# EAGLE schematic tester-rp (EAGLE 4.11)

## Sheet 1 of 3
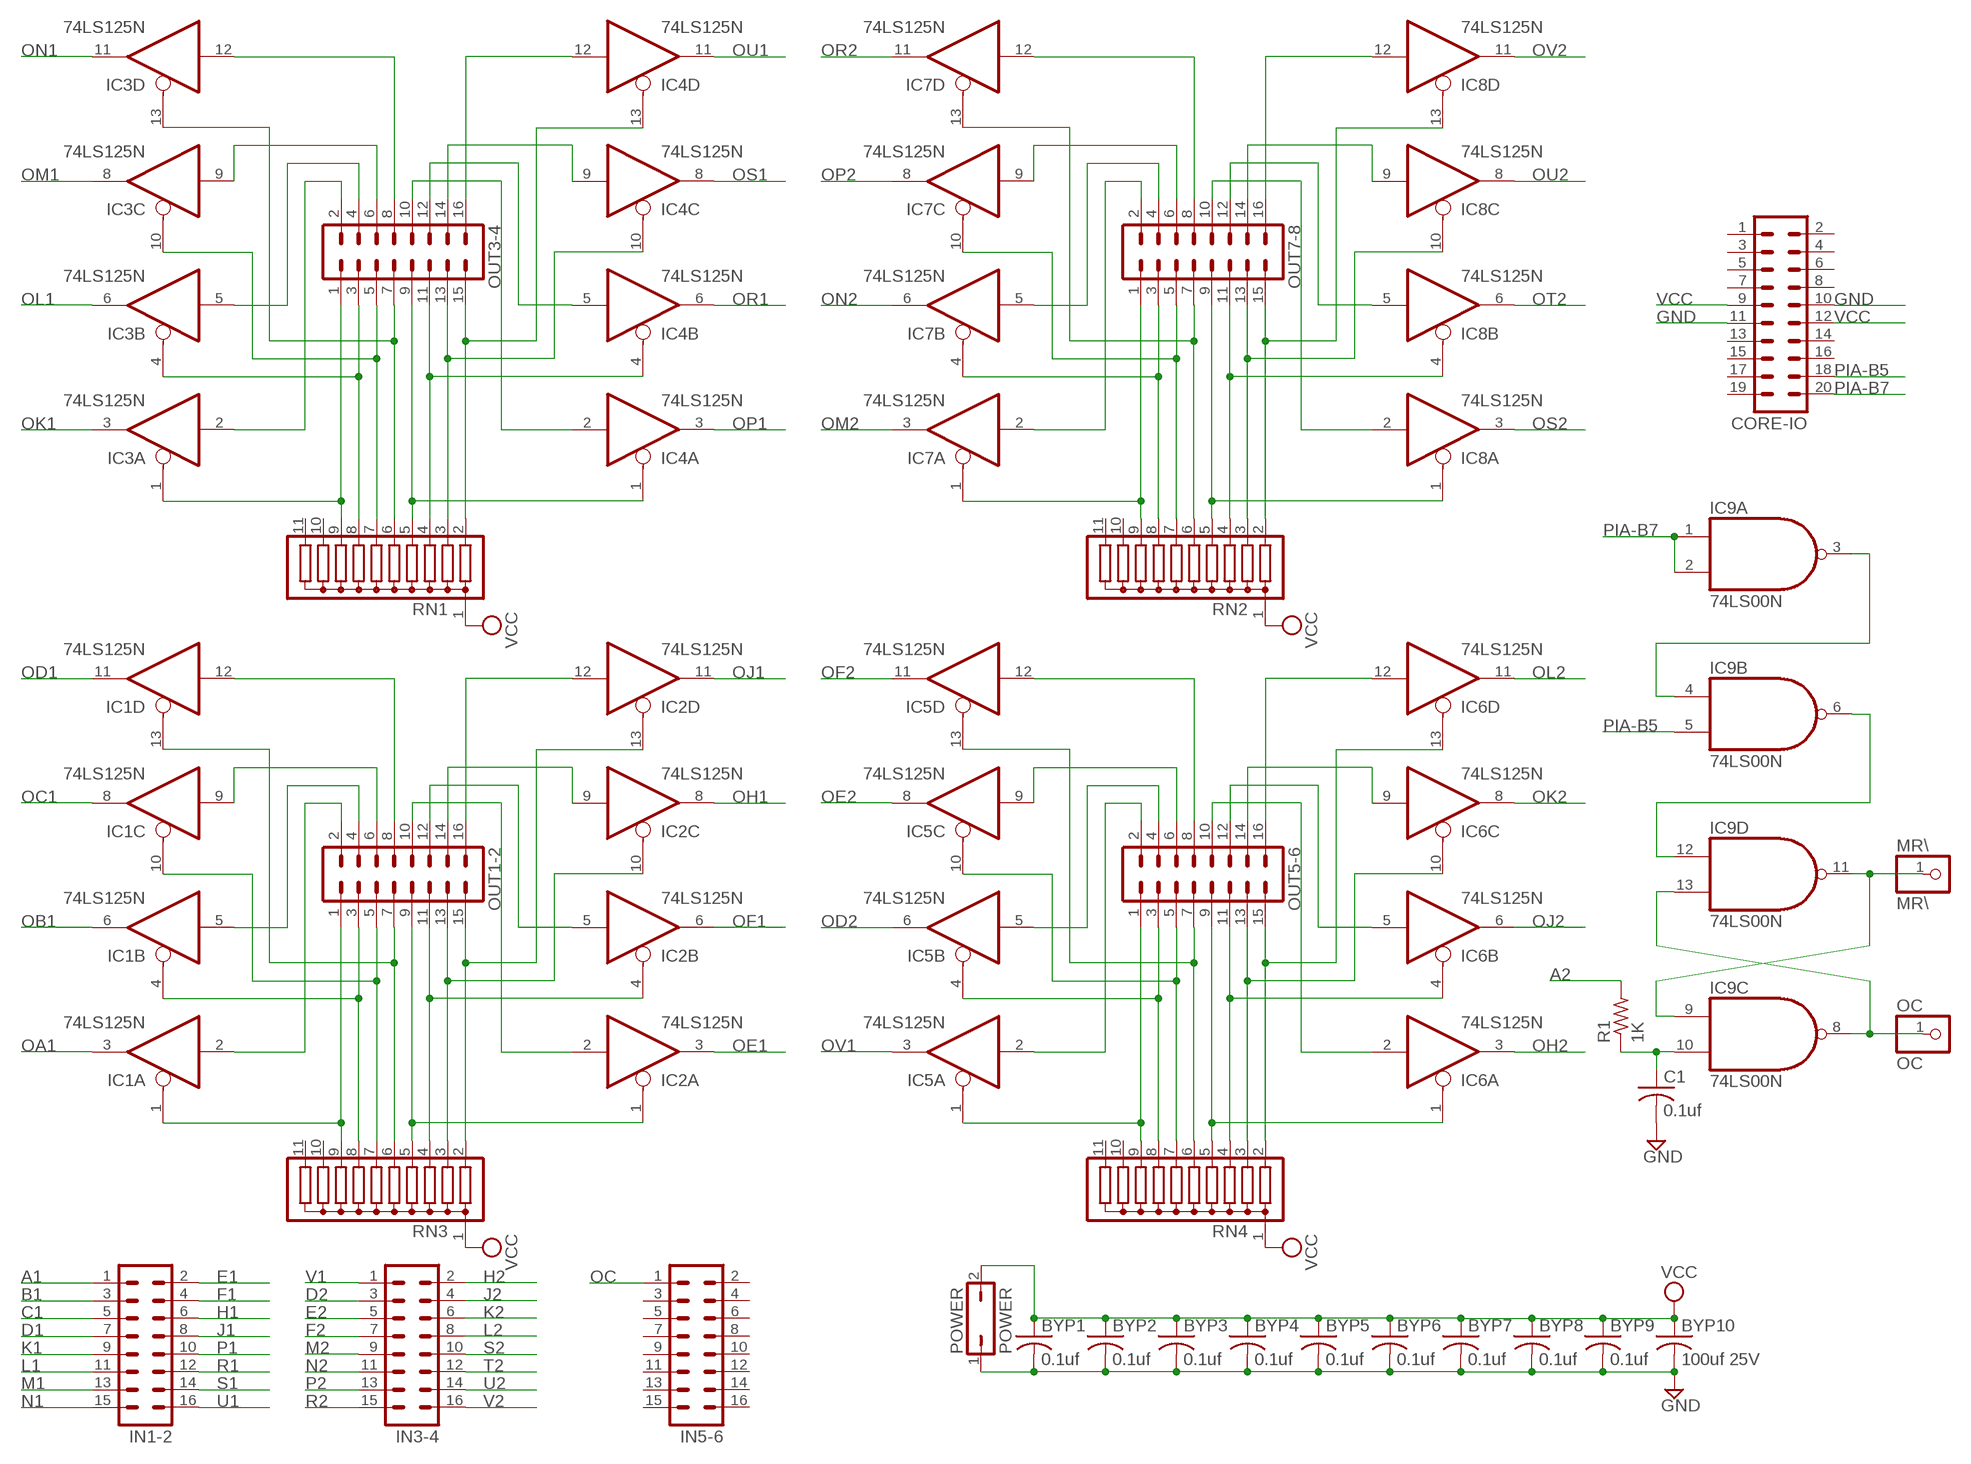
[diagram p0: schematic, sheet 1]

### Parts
BYP1  0.1uf  C-US050-025X075  [C050-025X075]
BYP2  0.1uf  C-US050-025X075  [C050-025X075]
BYP3  0.1uf  C-US050-025X075  [C050-025X075]
BYP4  0.1uf  C-US050-025X075  [C050-025X075]
BYP5  0.1uf  C-US050-025X075  [C050-025X075]
BYP6  0.1uf  C-US050-025X075  [C050-025X075]
BYP7  0.1uf  C-US050-025X075  [C050-025X075]
BYP8  0.1uf  C-US050-025X075  [C050-025X075]
BYP9  0.1uf  C-US050-025X075  [C050-025X075]
BYP10  100uf 25V  C-US150-064X183  [C150-064X183]
C1  0.1uf  C-US050-025X075  [C050-025X075]
CORE-IO  MA10-2  [MA10-2]
IC1  74LS125N  [DIL14]
IC2  74LS125N  [DIL14]
IC3  74LS125N  [DIL14]
IC4  74LS125N  [DIL14]
IC5  74LS125N  [DIL14]
IC6  74LS125N  [DIL14]
IC7  74LS125N  [DIL14]
IC8  74LS125N  [DIL14]
IC9  74LS00N  [DIL14]
IN1-2  MA08-2  [MA08-2]
IN3-4  MA08-2  [MA08-2]
IN5-6  MA08-2  [MA08-2]
MR\  MR\  PINHD-1X1  [1X01]
OC  OC  PINHD-1X1  [1X01]
OUT1-2  MA08-2  [MA08-2]
OUT3-4  MA08-2  [MA08-2]
OUT5-6  MA08-2  [MA08-2]
OUT7-8  MA08-2  [MA08-2]
POWER  POWER  JP1Q  [JP1]
R1  1K  R-US_0207/10  [0207/10]
RN1  G10R  [SIL11]
RN2  G10R  [SIL11]
RN3  G10R  [SIL11]
RN4  G10R  [SIL11]

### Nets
A1: IN1-2.1 ; also sheet 3
A2: R1.2 ; also sheet 3
B1: IN1-2.3 ; also sheet 3
C1: IN1-2.5 ; also sheet 3
D1: IN1-2.7 ; also sheet 3
D2: IN3-4.3 ; also sheet 3
E1: IN1-2.2 ; also sheet 3
E2: IN3-4.5 ; also sheet 3
F1: IN1-2.4 ; also sheet 3
F2: IN3-4.7 ; also sheet 3
GND [Power]: BYP1.2 BYP2.2 BYP3.2 BYP4.2 BYP5.2 BYP6.2 BYP7.2 BYP8.2 BYP9.2 BYP10.2 C1.2 CORE-IO.10 CORE-IO.11 POWER.1 ; also sheet 3
H1: IN1-2.6 ; also sheet 3
H2: IN3-4.2 ; also sheet 3
J1: IN1-2.8 ; also sheet 3
J2: IN3-4.4 ; also sheet 3
K1: IN1-2.9 ; also sheet 3
K2: IN3-4.6 ; also sheet 3
L1: IN1-2.11 ; also sheet 3
L2: IN3-4.8 ; also sheet 3
M1: IN1-2.13 ; also sheet 3
M2: IN3-4.9 ; also sheet 3
MR\: IC9.9(C:I0) IC9.11(D:O) MR\.1
N1: IN1-2.15 ; also sheet 3
N2: IN3-4.11 ; also sheet 3
N$1: IC9.6(B:O) IC9.12(D:I0)
N$2: IC9.3(A:O) IC9.4(B:I0)
N$5: C1.1 IC9.10(C:I1) R1.1
N$53: IC1.1(A:OE) OUT1-2.1 RN3.9
N$54: IC1.4(B:OE) OUT1-2.3 RN3.8
N$55: IC1.10(C:OE) OUT1-2.5 RN3.7
N$56: IC1.13(D:OE) OUT1-2.7 RN3.6
N$57: IC1.2(A:I) OUT1-2.2
N$58: IC1.5(B:I) OUT1-2.4
N$59: IC1.9(C:I) OUT1-2.6
N$60: IC1.12(D:I) OUT1-2.8
N$61: IC5.4(B:OE) OUT5-6.3 RN4.8
N$62: IC2.10(C:OE) OUT1-2.13 RN3.3
N$63: IC2.4(B:OE) OUT1-2.11 RN3.4
N$64: IC2.1(A:OE) OUT1-2.9 RN3.5
N$65: IC2.2(A:I) OUT1-2.10
N$66: IC2.5(B:I) OUT1-2.12
N$67: IC2.9(C:I) OUT1-2.14
N$68: IC2.12(D:I) OUT1-2.16
N$138: IC5.13(D:OE) OUT5-6.7 RN4.6
N$139: IC2.13(D:OE) OUT1-2.15 RN3.2
N$140: IC5.2(A:I) OUT5-6.2
N$141: IC5.5(B:I) OUT5-6.4
N$142: IC5.9(C:I) OUT5-6.6
N$143: IC5.12(D:I) OUT5-6.8
N$144: IC6.10(C:OE) OUT5-6.13 RN4.3
N$145: IC6.4(B:OE) OUT5-6.11 RN4.4
N$146: IC6.1(A:OE) OUT5-6.9 RN4.5
N$147: IC6.2(A:I) OUT5-6.10
N$148: IC6.9(C:I) OUT5-6.14
N$149: IC6.12(D:I) OUT5-6.16
N$150: IC5.1(A:OE) OUT5-6.1 RN4.9
N$151: IC5.10(C:OE) OUT5-6.5 RN4.7
N$152: IC6.5(B:I) OUT5-6.12
N$153: IC6.13(D:OE) OUT5-6.15 RN4.2
N$154: IC3.4(B:OE) OUT3-4.3 RN1.8
N$155: IC3.13(D:OE) OUT3-4.7 RN1.6
N$156: IC3.2(A:I) OUT3-4.2
N$157: IC3.5(B:I) OUT3-4.4
N$158: IC3.9(C:I) OUT3-4.6
N$159: IC3.12(D:I) OUT3-4.8
N$160: IC4.10(C:OE) OUT3-4.13 RN1.3
N$161: IC4.4(B:OE) OUT3-4.11 RN1.4
N$162: IC4.1(A:OE) OUT3-4.9 RN1.5
N$163: IC4.2(A:I) OUT3-4.10
N$164: IC4.9(C:I) OUT3-4.14
N$165: IC4.12(D:I) OUT3-4.16
N$166: IC3.1(A:OE) OUT3-4.1 RN1.9
N$167: IC3.10(C:OE) OUT3-4.5 RN1.7
N$168: IC4.5(B:I) OUT3-4.12
N$169: IC4.13(D:OE) OUT3-4.15 RN1.2
N$170: IC7.4(B:OE) OUT7-8.3 RN2.8
N$171: IC7.13(D:OE) OUT7-8.7 RN2.6
N$172: IC7.2(A:I) OUT7-8.2
N$173: IC7.5(B:I) OUT7-8.4
N$174: IC7.9(C:I) OUT7-8.6
N$175: IC7.12(D:I) OUT7-8.8
N$176: IC8.10(C:OE) OUT7-8.13 RN2.3
N$177: IC8.4(B:OE) OUT7-8.11 RN2.4
N$178: IC8.1(A:OE) OUT7-8.9 RN2.5
N$179: IC8.2(A:I) OUT7-8.10
N$180: IC8.9(C:I) OUT7-8.14
N$181: IC8.12(D:I) OUT7-8.16
N$182: IC7.1(A:OE) OUT7-8.1 RN2.9
N$183: IC7.10(C:OE) OUT7-8.5 RN2.7
N$184: IC8.5(B:I) OUT7-8.12
N$185: IC8.13(D:OE) OUT7-8.15 RN2.2
OA1: IC1.3(A:O) ; also sheet 3
OB1: IC1.6(B:O) ; also sheet 3
OC: IC9.8(C:O) IC9.13(D:I1) IN5-6.1 OC.1
OC1: IC1.8(C:O) ; also sheet 3
OD1: IC1.11(D:O) ; also sheet 3
OD2: IC5.6(B:O) ; also sheet 3
OE1: IC2.3(A:O) ; also sheet 3
OE2: IC5.8(C:O) ; also sheet 3
OF1: IC2.6(B:O) ; also sheet 3
OF2: IC5.11(D:O) ; also sheet 3
OH1: IC2.8(C:O) ; also sheet 3
OH2: IC6.3(A:O) ; also sheet 3
OJ1: IC2.11(D:O) ; also sheet 3
OJ2: IC6.6(B:O) ; also sheet 3
OK1: IC3.3(A:O) ; also sheet 3
OK2: IC6.8(C:O) ; also sheet 3
OL1: IC3.6(B:O) ; also sheet 3
OL2: IC6.11(D:O) ; also sheet 3
OM1: IC3.8(C:O) ; also sheet 3
OM2: IC7.3(A:O) ; also sheet 3
ON1: IC3.11(D:O) ; also sheet 3
ON2: IC7.6(B:O) ; also sheet 3
OP1: IC4.3(A:O) ; also sheet 3
OP2: IC7.8(C:O) ; also sheet 3
OR1: IC4.6(B:O) ; also sheet 3
OR2: IC7.11(D:O) ; also sheet 3
OS1: IC4.8(C:O) ; also sheet 3
OS2: IC8.3(A:O) ; also sheet 3
OT2: IC8.6(B:O) ; also sheet 3
OU1: IC4.11(D:O) ; also sheet 3
OU2: IC8.8(C:O) ; also sheet 3
OV1: IC5.3(A:O) ; also sheet 3
OV2: IC8.11(D:O) ; also sheet 3
P1: IN1-2.10 ; also sheet 3
P2: IN3-4.13 ; also sheet 3
PIA-B5: CORE-IO.18 IC9.5(B:I1)
PIA-B7: CORE-IO.20 IC9.1(A:I0) IC9.2(A:I1)
R1: IN1-2.12 ; also sheet 3
R2: IN3-4.15 ; also sheet 3
S1: IN1-2.14 ; also sheet 3
S2: IN3-4.10 ; also sheet 3
T2: IN3-4.12 ; also sheet 3
U1: IN1-2.16 ; also sheet 3
U2: IN3-4.14 ; also sheet 3
V1: IN3-4.1 ; also sheet 3
V2: IN3-4.16 ; also sheet 3
VCC [Power]: BYP1.1 BYP2.1 BYP3.1 BYP4.1 BYP5.1 BYP6.1 BYP7.1 BYP8.1 BYP9.1 BYP10.1 CORE-IO.9 CORE-IO.12 POWER.2 RN1.1 RN2.1 RN3.1 RN4.1 ; also sheet 3
Unconnected: CORE-IO.1 CORE-IO.2 CORE-IO.3 CORE-IO.4 CORE-IO.5 CORE-IO.6 CORE-IO.7 CORE-IO.8 CORE-IO.13 CORE-IO.14 CORE-IO.15 CORE-IO.16 CORE-IO.17 CORE-IO.19 IN5-6.2 IN5-6.3 IN5-6.4 IN5-6.5 IN5-6.6 IN5-6.7 IN5-6.8 IN5-6.9 IN5-6.10 IN5-6.11 IN5-6.12 IN5-6.13 IN5-6.14 IN5-6.15 IN5-6.16 RN1.10 RN1.11 RN2.10 RN2.11 RN3.10 RN3.11 RN4.10 RN4.11

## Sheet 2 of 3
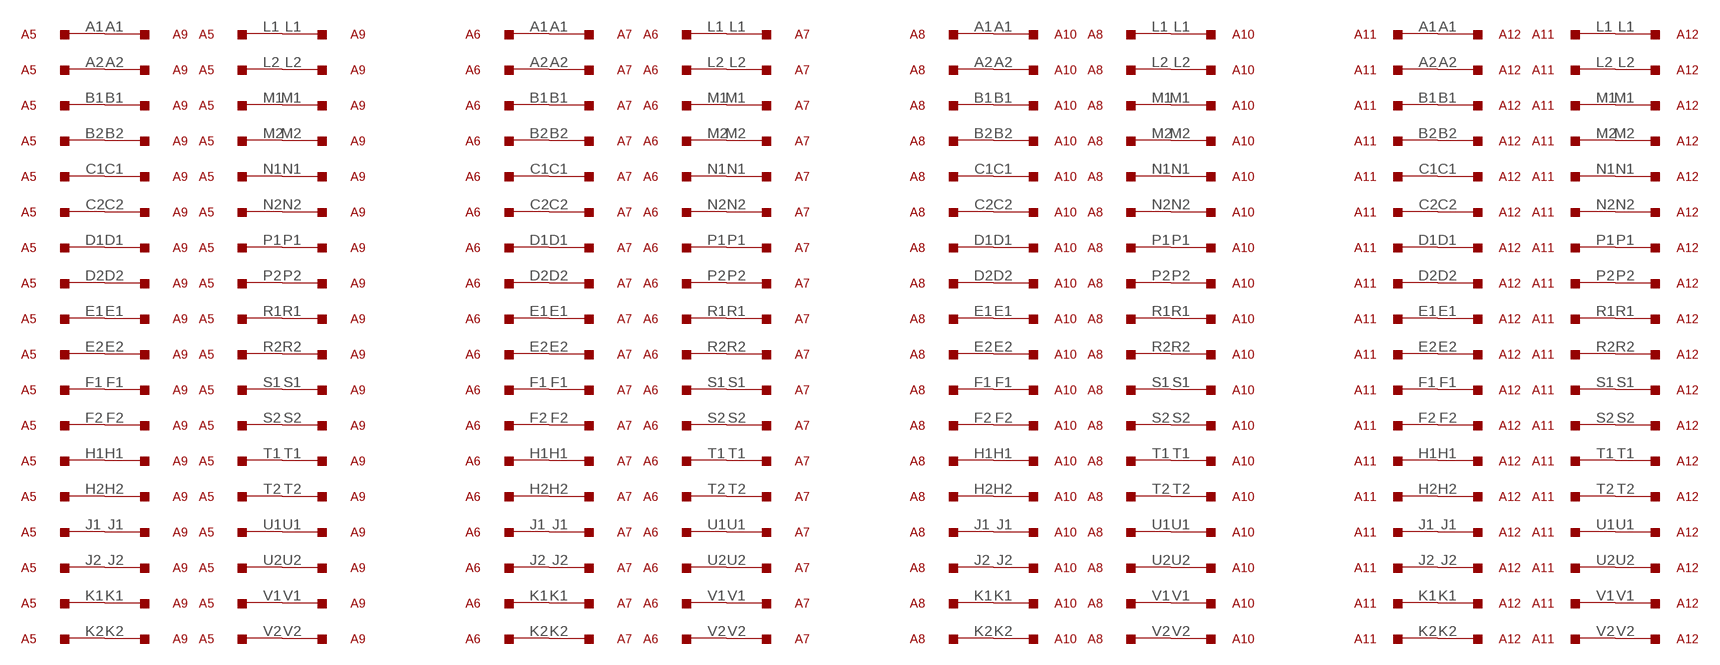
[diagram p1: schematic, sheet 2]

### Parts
A5  M916  [H807]
A6  M916  [H807]
A7  M916  [H807]
A8  M916  [H807]
A9  M916  [H807]
A10  M916  [H807]
A11  M916  [H807]
A12  M916  [H807]

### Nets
N$26: A5.L1 A9.L1
N$33: A5.L2 A9.L2
N$34: A5.M1 A9.M1
N$35: A5.M2 A9.M2
N$36: A5.N1 A9.N1
N$49: A5.N2 A9.N2
N$50: A5.P1 A9.P1
N$51: A5.P2 A9.P2
N$52: A5.R1 A9.R1
N$69: A5.R2 A9.R2
N$70: A5.S1 A9.S1
N$71: A5.S2 A9.S2
N$72: A5.T1 A9.T1
N$73: A5.T2 A9.T2
N$74: A5.U1 A9.U1
N$75: A5.U2 A9.U2
N$76: A5.V1 A9.V1
N$81: A5.V2 A9.V2
N$82: A5.A1 A9.A1
N$83: A5.A2 A9.A2
N$84: A5.B1 A9.B1
N$85: A5.B2 A9.B2
N$86: A5.C1 A9.C1
N$87: A5.C2 A9.C2
N$88: A5.D1 A9.D1
N$89: A5.D2 A9.D2
N$90: A5.E1 A9.E1
N$91: A5.E2 A9.E2
N$92: A5.F1 A9.F1
N$93: A5.F2 A9.F2
N$95: A5.H1 A9.H1
N$96: A5.H2 A9.H2
N$97: A5.J1 A9.J1
N$98: A5.J2 A9.J2
N$99: A5.K1 A9.K1
N$100: A5.K2 A9.K2
N$113: A6.L1 A7.L1
N$114: A6.L2 A7.L2
N$115: A6.M1 A7.M1
N$116: A6.M2 A7.M2
N$117: A6.N1 A7.N1
N$118: A6.N2 A7.N2
N$119: A6.P1 A7.P1
N$120: A6.P2 A7.P2
N$121: A6.R1 A7.R1
N$122: A6.R2 A7.R2
N$123: A6.S1 A7.S1
N$137: A6.S2 A7.S2
N$186: A6.T1 A7.T1
N$187: A6.T2 A7.T2
N$188: A6.U1 A7.U1
N$189: A6.U2 A7.U2
N$190: A6.V1 A7.V1
N$191: A6.V2 A7.V2
N$192: A6.A1 A7.A1
N$193: A6.A2 A7.A2
N$194: A6.B1 A7.B1
N$195: A6.B2 A7.B2
N$196: A6.C1 A7.C1
N$197: A6.C2 A7.C2
N$198: A6.D1 A7.D1
N$199: A6.D2 A7.D2
N$200: A6.E1 A7.E1
N$201: A6.E2 A7.E2
N$202: A6.F1 A7.F1
N$203: A6.F2 A7.F2
N$204: A6.H1 A7.H1
N$205: A6.H2 A7.H2
N$206: A6.J1 A7.J1
N$207: A6.J2 A7.J2
N$208: A6.K1 A7.K1
N$209: A6.K2 A7.K2
N$210: A8.L1 A10.L1
N$211: A8.L2 A10.L2
N$212: A8.M1 A10.M1
N$213: A8.M2 A10.M2
N$214: A8.N1 A10.N1
N$215: A8.N2 A10.N2
N$216: A8.P1 A10.P1
N$217: A8.P2 A10.P2
N$218: A8.R1 A10.R1
N$219: A8.R2 A10.R2
N$220: A8.S1 A10.S1
N$221: A8.S2 A10.S2
N$222: A8.T1 A10.T1
N$223: A8.T2 A10.T2
N$224: A8.U1 A10.U1
N$225: A8.U2 A10.U2
N$226: A8.V1 A10.V1
N$227: A8.V2 A10.V2
N$228: A8.A1 A10.A1
N$229: A8.A2 A10.A2
N$230: A8.B1 A10.B1
N$231: A8.B2 A10.B2
N$232: A8.C1 A10.C1
N$233: A8.C2 A10.C2
N$234: A8.D1 A10.D1
N$235: A8.D2 A10.D2
N$236: A8.E1 A10.E1
N$237: A8.E2 A10.E2
N$238: A8.F1 A10.F1
N$239: A8.F2 A10.F2
N$240: A8.H1 A10.H1
N$241: A8.H2 A10.H2
N$242: A8.J1 A10.J1
N$243: A8.J2 A10.J2
N$244: A8.K1 A10.K1
N$245: A8.K2 A10.K2
N$246: A11.L1 A12.L1
N$247: A11.L2 A12.L2
N$248: A11.M1 A12.M1
N$249: A11.M2 A12.M2
N$250: A11.N1 A12.N1
N$251: A11.N2 A12.N2
N$252: A11.P1 A12.P1
N$253: A11.P2 A12.P2
N$254: A11.R1 A12.R1
N$255: A11.R2 A12.R2
N$256: A11.S1 A12.S1
N$257: A11.S2 A12.S2
N$258: A11.T1 A12.T1
N$259: A11.T2 A12.T2
N$260: A11.U1 A12.U1
N$261: A11.U2 A12.U2
N$262: A11.V1 A12.V1
N$263: A11.V2 A12.V2
N$264: A11.A1 A12.A1
N$265: A11.A2 A12.A2
N$266: A11.B1 A12.B1
N$267: A11.B2 A12.B2
N$268: A11.C1 A12.C1
N$269: A11.C2 A12.C2
N$270: A11.D1 A12.D1
N$271: A11.D2 A12.D2
N$272: A11.E1 A12.E1
N$273: A11.E2 A12.E2
N$274: A11.F1 A12.F1
N$275: A11.F2 A12.F2
N$276: A11.H1 A12.H1
N$277: A11.H2 A12.H2
N$278: A11.J1 A12.J1
N$279: A11.J2 A12.J2
N$280: A11.K1 A12.K1
N$281: A11.K2 A12.K2

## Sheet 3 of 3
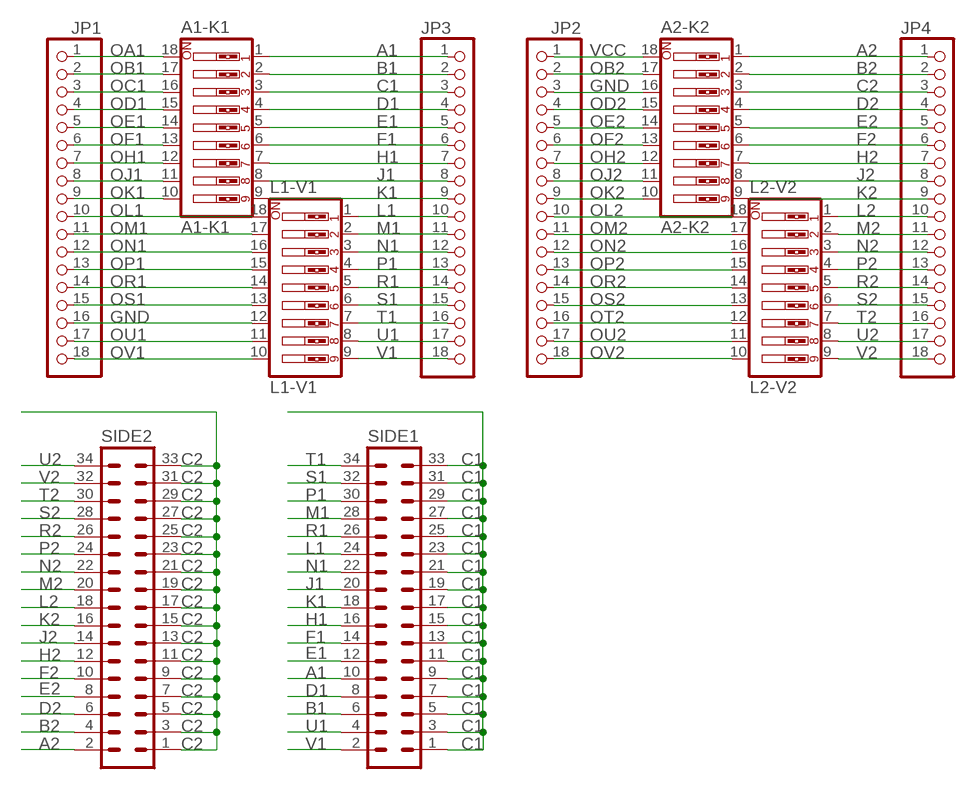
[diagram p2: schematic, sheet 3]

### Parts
A1-K1  A1-K1  SW_DIP-9  [EDG-09]
A2-K2  A2-K2  SW_DIP-9  [EDG-09]
JP1  PINHD-1X18  [1X18]
JP2  PINHD-1X18  [1X18]
JP3  PINHD-1X18  [1X18]
JP4  PINHD-1X18  [1X18]
L1-V1  L1-V1  SW_DIP-9  [EDG-09]
L2-V2  L2-V2  SW_DIP-9  [EDG-09]
SIDE1  MA17-2  [MA17-2]
SIDE2  MA17-2  [MA17-2]

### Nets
A1: A1-K1.1 JP3.1 SIDE1.10 ; also sheet 1
A2: A2-K2.1 JP4.1 SIDE2.2 ; also sheet 1
B1: A1-K1.2 JP3.2 SIDE1.6 ; also sheet 1
B2: A2-K2.2 JP4.2 SIDE2.4
C1: A1-K1.3 JP3.3 SIDE1.1 SIDE1.3 SIDE1.5 SIDE1.7 SIDE1.9 SIDE1.11 SIDE1.13 SIDE1.15 SIDE1.17 SIDE1.19 SIDE1.21 SIDE1.23 SIDE1.25 SIDE1.27 SIDE1.29 SIDE1.31 SIDE1.33 ; also sheet 1
C2: A2-K2.3 JP4.3 SIDE2.1 SIDE2.3 SIDE2.5 SIDE2.7 SIDE2.9 SIDE2.11 SIDE2.13 SIDE2.15 SIDE2.17 SIDE2.19 SIDE2.21 SIDE2.23 SIDE2.25 SIDE2.27 SIDE2.29 SIDE2.31 SIDE2.33
D1: A1-K1.4 JP3.4 SIDE1.8 ; also sheet 1
D2: A2-K2.4 JP4.4 SIDE2.6 ; also sheet 1
E1: A1-K1.5 JP3.5 SIDE1.12 ; also sheet 1
E2: A2-K2.5 JP4.5 SIDE2.8 ; also sheet 1
F1: A1-K1.6 JP3.6 SIDE1.14 ; also sheet 1
F2: A2-K2.6 JP4.6 SIDE2.10 ; also sheet 1
GND [Power]: A2-K2.16 JP1.16 JP2.3 L1-V1.12 ; also sheet 1
H1: A1-K1.7 JP3.7 SIDE1.16 ; also sheet 1
H2: A2-K2.7 JP4.7 SIDE2.12 ; also sheet 1
J1: A1-K1.8 JP3.8 SIDE1.20 ; also sheet 1
J2: A2-K2.8 JP4.8 SIDE2.14 ; also sheet 1
K1: A1-K1.9 JP3.9 SIDE1.18 ; also sheet 1
K2: A2-K2.9 JP4.9 SIDE2.16 ; also sheet 1
L1: JP3.10 L1-V1.1 SIDE1.24 ; also sheet 1
L2: JP4.10 L2-V2.1 SIDE2.18 ; also sheet 1
M1: JP3.11 L1-V1.2 SIDE1.28 ; also sheet 1
M2: JP4.11 L2-V2.2 SIDE2.20 ; also sheet 1
N1: JP3.12 L1-V1.3 SIDE1.22 ; also sheet 1
N2: JP4.12 L2-V2.3 SIDE2.22 ; also sheet 1
OA1: A1-K1.18 JP1.1 ; also sheet 1
OB1: A1-K1.17 JP1.2 ; also sheet 1
OB2: A2-K2.17 JP2.2
OC1: A1-K1.16 JP1.3 ; also sheet 1
OD1: A1-K1.15 JP1.4 ; also sheet 1
OD2: A2-K2.15 JP2.4 ; also sheet 1
OE1: A1-K1.14 JP1.5 ; also sheet 1
OE2: A2-K2.14 JP2.5 ; also sheet 1
OF1: A1-K1.13 JP1.6 ; also sheet 1
OF2: A2-K2.13 JP2.6 ; also sheet 1
OH1: A1-K1.12 JP1.7 ; also sheet 1
OH2: A2-K2.12 JP2.7 ; also sheet 1
OJ1: A1-K1.11 JP1.8 ; also sheet 1
OJ2: A2-K2.11 JP2.8 ; also sheet 1
OK1: A1-K1.10 JP1.9 ; also sheet 1
OK2: A2-K2.10 JP2.9 ; also sheet 1
OL1: JP1.10 L1-V1.18 ; also sheet 1
OL2: JP2.10 L2-V2.18 ; also sheet 1
OM1: JP1.11 L1-V1.17 ; also sheet 1
OM2: JP2.11 L2-V2.17 ; also sheet 1
ON1: JP1.12 L1-V1.16 ; also sheet 1
ON2: JP2.12 L2-V2.16 ; also sheet 1
OP1: JP1.13 L1-V1.15 ; also sheet 1
OP2: JP2.13 L2-V2.15 ; also sheet 1
OR1: JP1.14 L1-V1.14 ; also sheet 1
OR2: JP2.14 L2-V2.14 ; also sheet 1
OS1: JP1.15 L1-V1.13 ; also sheet 1
OS2: JP2.15 L2-V2.13 ; also sheet 1
OT2: JP2.16 L2-V2.12 ; also sheet 1
OU1: JP1.17 L1-V1.11 ; also sheet 1
OU2: JP2.17 L2-V2.11 ; also sheet 1
OV1: JP1.18 L1-V1.10 ; also sheet 1
OV2: JP2.18 L2-V2.10 ; also sheet 1
P1: JP3.13 L1-V1.4 SIDE1.30 ; also sheet 1
P2: JP4.13 L2-V2.4 SIDE2.24 ; also sheet 1
R1: JP3.14 L1-V1.5 SIDE1.26 ; also sheet 1
R2: JP4.14 L2-V2.5 SIDE2.26 ; also sheet 1
S1: JP3.15 L1-V1.6 SIDE1.32 ; also sheet 1
S2: JP4.15 L2-V2.6 SIDE2.28 ; also sheet 1
T1: JP3.16 L1-V1.7 SIDE1.34
T2: JP4.16 L2-V2.7 SIDE2.30 ; also sheet 1
U1: JP3.17 L1-V1.8 SIDE1.4 ; also sheet 1
U2: JP4.17 L2-V2.8 SIDE2.34 ; also sheet 1
V1: JP3.18 L1-V1.9 SIDE1.2 ; also sheet 1
V2: JP4.18 L2-V2.9 SIDE2.32 ; also sheet 1
VCC [Power]: A2-K2.18 JP2.1 ; also sheet 1

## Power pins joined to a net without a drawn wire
GND: IC1.7(P:GND) IC2.7(P:GND) IC3.7(P:GND) IC4.7(P:GND) IC5.7(P:GND) IC6.7(P:GND) IC7.7(P:GND) IC8.7(P:GND) IC9.7(P:GND)
VCC: IC1.14(P:VCC) IC2.14(P:VCC) IC3.14(P:VCC) IC4.14(P:VCC) IC5.14(P:VCC) IC6.14(P:VCC) IC7.14(P:VCC) IC8.14(P:VCC) IC9.14(P:VCC)

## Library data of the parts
A1-K1 A2-K2 L1-V1 L2-V2 = special:SW_DIP-9: DIP SWITCH
A5-A12 = dec-m:M916: Simple 36 pin connector/wire cable
BYP1-BYP10 C1 = rcl:C-US: CAPACITOR, American symbol
CORE-IO = con-lstb:MA10-2: PIN HEADER
IC1-IC8 = 74xx-jameco:74*125: Quad bus BUFFER, 3-state
IC9 = 74xx-jameco:74*00: Quad 2-input NAND gate
IN1-2 IN3-4 IN5-6 OUT1-2 OUT3-4 OUT5-6 OUT7-8 = con-lstb:MA08-2: PIN HEADER
JP1-JP4 = pinhead:PINHD-1X18: PIN HEADER
MR\ OC = pinhead:PINHD-1X1: PIN HEADER
POWER = jumper:JP1Q: JUMPER
R1 = rcl:R-US_: RESISTOR, American symbol
RN1-RN4 = resistor-sil:G10R: SIL RESISTOR
SIDE1 SIDE2 = con-lstb:MA17-2: PIN HEADER

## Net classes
1 Power: width 0.305 mm, drill 0.305 mm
